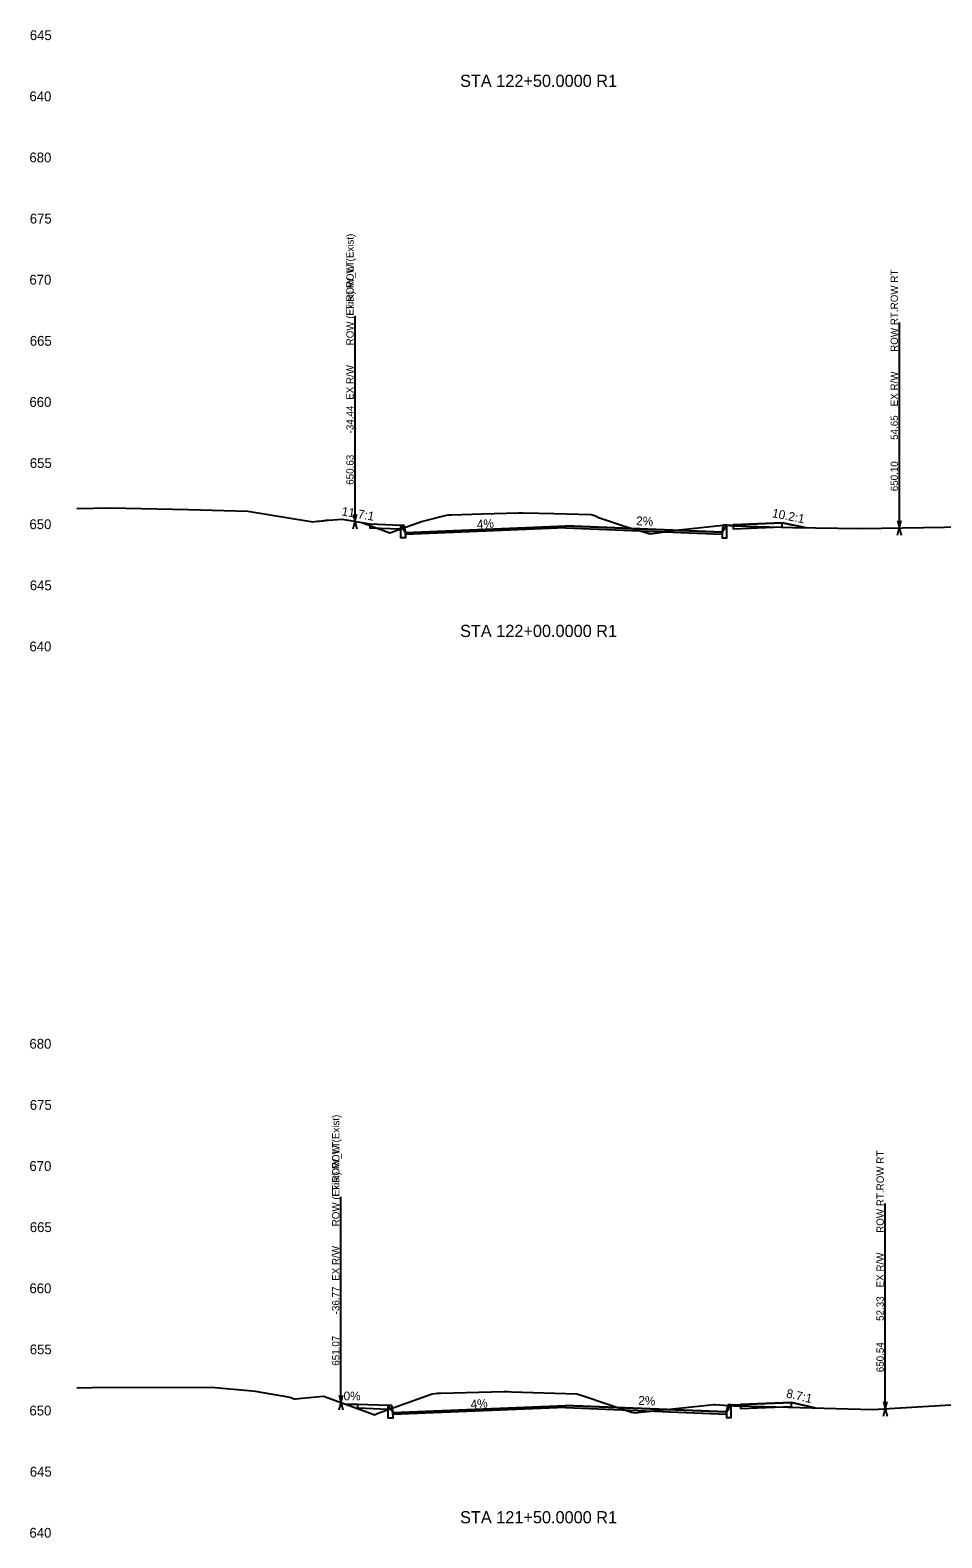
# Model space of a CAD drawing. Extents: x 2 to 741, y 16 to 2207.
# Drawn here: x 2.4 to 151.6, y 560 to 806.6 of the extents above; entities that cross this region are included whole.
import ezdxf

# ---------------------------------------------------------------- set-up
doc = ezdxf.new("R2010")
doc.units = 0
for name, color, linetype in [('Draft_XS_Feature_Name', 7, 'Continuous'), ('Draft_XS_Label', 7, 'Continuous'), ('Draft_XS_Point_Label_Indicator', 7, 'Continuous'), ('Draft_XS_Terminator', 7, 'Continuous'), ('Draft_XS_Text', 7, 'Continuous'), ('E_ROW', 7, 'Continuous'), ('E_Terrain_Exterior', 7, 'Continuous'), ('E_Terrain_Points_Low', 7, 'Continuous'), ('Grade_Veg_Grass', 7, 'Continuous'), ('P_XS_Sections', 7, 'Continuous'), ('Road_Curb', 7, 'Continuous'), ('Road_Pave_Asphalt', 7, 'Continuous'), ('Road_Sidewalk', 7, 'Continuous'), ('Terrain_Design', 7, 'Continuous')]:
    doc.layers.add(name, color=color, linetype=linetype)

msp = doc.modelspace()

# ---------------------------------------------------------------- linework, layer by layer
at = {"layer": 'Draft_XS_Terminator'}
for p, q in [((55.56, 726.26), (55.56, 748.26)), ((55.56, 726.26), (55.56, 748.26)), ((144.65, 725.2), (144.65, 747.2)), ((53.23, 582.14), (53.23, 604.14)), ((53.23, 582.14), (53.23, 604.14)), ((142.33, 581.07), (142.33, 603.07))]:
    msp.add_line(p, q, dxfattribs=at)
at = {"layer": 'E_ROW'}
for p, q in [((55.56, 726.26), (55.56, 759.86)), ((55.56, 726.26), (55.56, 759.86)), ((144.65, 725.2), (144.65, 758.8)), ((55.26, 725.06), (55.86, 727.46)), ((55.26, 727.46), (55.86, 725.06)), ((55.26, 725.06), (55.86, 727.46)), ((55.26, 727.46), (55.86, 725.06)), ((144.35, 724), (144.95, 726.4)), ((144.35, 726.4), (144.95, 724)), ((53.23, 582.14), (53.23, 615.74)), ((53.23, 582.14), (53.23, 615.74)), ((142.33, 581.07), (142.33, 614.67)), ((52.93, 580.94), (53.53, 583.34)), ((52.93, 583.34), (53.53, 580.94)), ((52.93, 580.94), (53.53, 583.34)), ((52.93, 583.34), (53.53, 580.94)), ((142.03, 579.87), (142.63, 582.27)), ((142.03, 582.27), (142.63, 579.87))]:
    msp.add_line(p, q, dxfattribs=at)
at = {"layer": 'E_Terrain_Exterior'}
for points in [[(10, 728.4), (15.46, 728.49), (28.27, 728.21), (38.02, 727.93), (48.33, 726.26), (48.53, 726.2), (48.57, 726.21), (48.99, 726.25), (49.38, 726.29), (49.38, 726.29), (49.74, 726.33), (50.04, 726.36), (50.27, 726.38), (50.47, 726.4), (50.66, 726.42), (50.83, 726.44), (50.96, 726.45), (51.09, 726.46), (51.19, 726.47), (53.43, 726.64), (56.67, 726.07), (61.23, 724.4), (66.42, 726.26), (70.52, 727.26), (70.98, 727.32), (71.34, 727.35), (76.35, 727.53), (82.32, 727.69), (82.69, 727.68), (83.07, 727.69), (88.15, 727.56), (94.21, 727.38), (94.91, 727.15), (95.37, 726.93), (99.8, 725.45), (103.87, 724.21), (108.64, 724.9), (115.73, 725.64), (116.19, 725.64), (117.55, 725.55), (127.18, 725.28), (138.29, 725.11), (155.48, 725.37)], [(10, 584.52), (12.6, 584.59), (26.97, 584.65), (32.66, 584.56), (38.69, 584.04), (39.19, 584), (44.86, 582.97), (45.61, 582.74), (45.7, 582.73), (45.77, 582.72), (50.4, 583.18), (58.36, 580.26), (58.73, 580.09), (59.18, 580.3), (68.19, 583.54), (68.23, 583.54), (69.02, 583.64), (69.59, 583.64), (79.94, 583.92), (79.97, 583.92), (80.62, 583.9), (81.18, 583.86), (91.81, 583.54), (91.84, 583.54), (93.07, 583.15), (100.79, 580.56), (101.28, 580.44), (113.8, 581.74), (114.33, 581.8), (114.46, 581.77), (117.49, 581.56), (118.47, 581.57), (140.22, 580.95), (164.97, 582.42)]]:
    msp.add_lwpolyline(points, dxfattribs=at)
at = {"layer": 'Grade_Veg_Grass'}
for points in [[(56.04, 726.18), (58.04, 725.84), (58.04, 725.84)], [(116.39, 725.66), (117.44, 725.7)], [(129.44, 725.24), (125.44, 726.02), (125.44, 726.02)], [(131, 581.21), (127, 582.13), (127, 582.13)], [(53.98, 581.86), (55.98, 581.86), (55.98, 581.86)], [(117.12, 581.73), (118.66, 581.79)]]:
    msp.add_lwpolyline(points, dxfattribs=at)
at = {"layer": 'Road_Curb'}
for points in [[(63.79, 724.47), (63.79, 723.56), (63.04, 723.56), (63.04, 725.64), (63.56, 725.64), (63.79, 724.47)], [(115.64, 724.5), (115.64, 723.58), (116.39, 723.58), (116.39, 725.66), (115.87, 725.66), (115.64, 724.5)], [(61.73, 580.49), (61.73, 579.57), (60.98, 579.57), (60.98, 581.66), (61.5, 581.66), (61.73, 580.49)], [(116.37, 580.57), (116.37, 579.65), (117.12, 579.65), (117.12, 581.73), (116.6, 581.73), (116.37, 580.57)]]:
    msp.add_lwpolyline(points, dxfattribs=at)
at = {"layer": 'Road_Pave_Asphalt'}
for points in [[(90, 725.52), (90, 725.19), (63.79, 724.14), (63.79, 724.47), (90, 725.52)], [(90, 725.52), (90, 725.19), (115.64, 724.16), (115.64, 724.5), (90, 725.52)], [(90, 581.62), (90, 581.29), (61.73, 580.16), (61.73, 580.49), (90, 581.62)], [(90, 581.62), (90, 581.29), (116.37, 580.23), (116.37, 580.57), (90, 581.62)]]:
    msp.add_lwpolyline(points, dxfattribs=at)
at = {"layer": 'Road_Sidewalk'}
for points in [[(63.04, 725.64), (63.04, 724.97), (58.04, 725.17), (58.04, 725.84), (63.04, 725.64)], [(117.44, 725.7), (117.44, 725.04), (125.44, 725.36), (125.44, 726.02), (117.44, 725.7)], [(118.66, 581.79), (118.66, 581.13), (127, 581.46), (127, 582.13), (118.66, 581.79)], [(60.98, 581.66), (60.98, 580.99), (55.98, 581.19), (55.98, 581.86), (60.98, 581.66)]]:
    msp.add_lwpolyline(points, dxfattribs=at)
at = {"layer": 'Terrain_Design'}
for points in [[(56.04, 726.18), (58.04, 725.84), (63.04, 725.64), (63.56, 725.64), (63.79, 724.47), (90, 725.52), (115.64, 724.5), (115.87, 725.66), (116.39, 725.66), (117.44, 725.7), (125.44, 726.02), (129.44, 725.24)], [(56.04, 726.18), (58.04, 725.84), (63.04, 725.64), (63.56, 724.83), (63.79, 724.47), (90, 725.52), (115.64, 724.5), (115.87, 724.85), (116.39, 725.66), (117.44, 725.7), (125.44, 726.02), (129.44, 725.24)], [(53.98, 581.86), (55.98, 581.86), (60.98, 581.66), (61.5, 581.66), (61.73, 580.49), (90, 581.62), (116.37, 580.57), (116.6, 581.73), (117.12, 581.73), (118.66, 581.79), (127, 582.13), (131, 581.21)], [(53.98, 581.86), (55.98, 581.86), (60.98, 581.66), (61.5, 580.85), (61.73, 580.49), (90, 581.62), (116.37, 580.57), (116.6, 580.92), (117.12, 581.73), (118.66, 581.79), (127, 582.13), (131, 581.21)]]:
    msp.add_lwpolyline(points, dxfattribs=at)

# ---------------------------------------------------------------- texts
at = {"layer": 'Draft_XS_Feature_Name'}
for s, p in [('ROW (Exist).ROW (Exist)', (55.32, 755.06)), ('ROW_LT.ROW_LT', (55.32, 755.06)), ('ROW RT.ROW RT', (144.41, 754)), ('ROW (Exist).ROW (Exist)', (52.99, 610.94)), ('ROW_LT.ROW_LT', (52.99, 610.94)), ('ROW RT.ROW RT', (142.09, 609.87))]:
    msp.add_text(s, height=1.2, rotation=90, dxfattribs=at).set_placement(p)
at = {"layer": 'Draft_XS_Label'}
for s, p in [('-34.44', (55.32, 740.66)), ('-34.44', (55.32, 740.66)), ('54.65', (144.41, 739.6)), ('650.63', (55.32, 732.26)), ('650.63', (55.32, 732.26)), ('650.10', (144.41, 731.2)), ('-36.77', (52.99, 596.54)), ('-36.77', (52.99, 596.54)), ('52.33', (142.09, 595.47)), ('651.07', (52.99, 588.14)), ('651.07', (52.99, 588.14)), ('650.54', (142.09, 587.07))]:
    msp.add_text(s, height=1.2, rotation=90, dxfattribs=at).set_placement(p)
at = {"layer": 'Draft_XS_Point_Label_Indicator'}
for p in [(56.02, 726.17), (58.02, 725.83), (63.02, 725.63), (63.54, 725.63), (115.86, 725.65), (116.38, 725.65), (117.43, 725.69), (125.43, 726.01), (129.43, 725.23), (63.77, 724.46), (63.77, 723.54), (115.63, 724.48), (115.63, 723.57), (126.99, 582.12), (53.97, 581.85), (55.97, 581.84), (60.97, 581.64), (61.49, 581.64), (61.72, 580.48), (116.36, 580.55), (116.36, 579.64), (116.59, 581.72), (117.11, 581.72), (118.65, 581.78), (130.99, 581.2), (61.72, 579.56)]:
    msp.add_text('X', height=0.024, dxfattribs=at).set_placement(p)
at = {"layer": 'Draft_XS_Text'}
for s, height, p in [('645', 1.608, (2.32, 805)), ('STA 122+50.0000 R1', 1.992, (72.74, 797.35)), ('640', 1.608, (2.26, 795)), ('680', 1.608, (2.26, 785)), ('675', 1.608, (2.32, 775)), ('670', 1.608, (2.26, 765)), ('665', 1.608, (2.32, 755)), ('660', 1.608, (2.26, 745)), ('655', 1.608, (2.32, 735)), ('650', 1.608, (2.26, 725)), ('645', 1.608, (2.32, 715)), ('STA 122+00.0000 R1', 1.992, (72.74, 707.35)), ('640', 1.608, (2.26, 705)), ('680', 1.608, (2.26, 640)), ('675', 1.608, (2.32, 630)), ('670', 1.608, (2.26, 620)), ('665', 1.608, (2.32, 610)), ('660', 1.608, (2.26, 600)), ('655', 1.608, (2.32, 590)), ('650', 1.608, (2.26, 580)), ('645', 1.608, (2.32, 570)), ('STA 121+50.0000 R1', 1.992, (72.74, 562.35)), ('640', 1.608, (2.26, 560))]:
    msp.add_text(s, height=height, dxfattribs=at).set_placement(p)
for s, rotation, p in [('11.7:1', 350.3011, (53.28, 727.26)), ('10.2:1', 348.9268, (123.72, 726.97)), ('4%', 4.2873, (75.54, 725.04)), ('2%', 357.7094, (101.53, 725.66)), ('0%', 359.7838, (53.67, 582.47)), ('4%', 4.1425, (74.51, 581.1)), ('2%', 357.7094, (101.89, 581.75)), ('8.7:1', 347.0579, (126.02, 582.97))]:
    msp.add_text(s, height=1.44, rotation=rotation, dxfattribs=at).set_placement(p)
at = {"layer": 'E_ROW'}
for p in [(55.32, 746.15), (55.32, 746.15), (144.41, 745.09), (52.99, 602.02), (52.99, 602.02), (142.09, 600.95)]:
    msp.add_text('EX R/W', height=1.2, rotation=90, dxfattribs=at).set_placement(p)
at = {"layer": 'E_Terrain_Points_Low'}
for p in [(89.99, 725.51), (89.99, 581.61)]:
    msp.add_text('X', height=0.024, dxfattribs=at).set_placement(p)
at = {"layer": 'P_XS_Sections'}
for p in [(10, 795), (10, 705), (10, 560)]:
    msp.add_text('-', height=0.0001, dxfattribs=at).set_placement(p)

doc.saveas('drawing.dxf')
